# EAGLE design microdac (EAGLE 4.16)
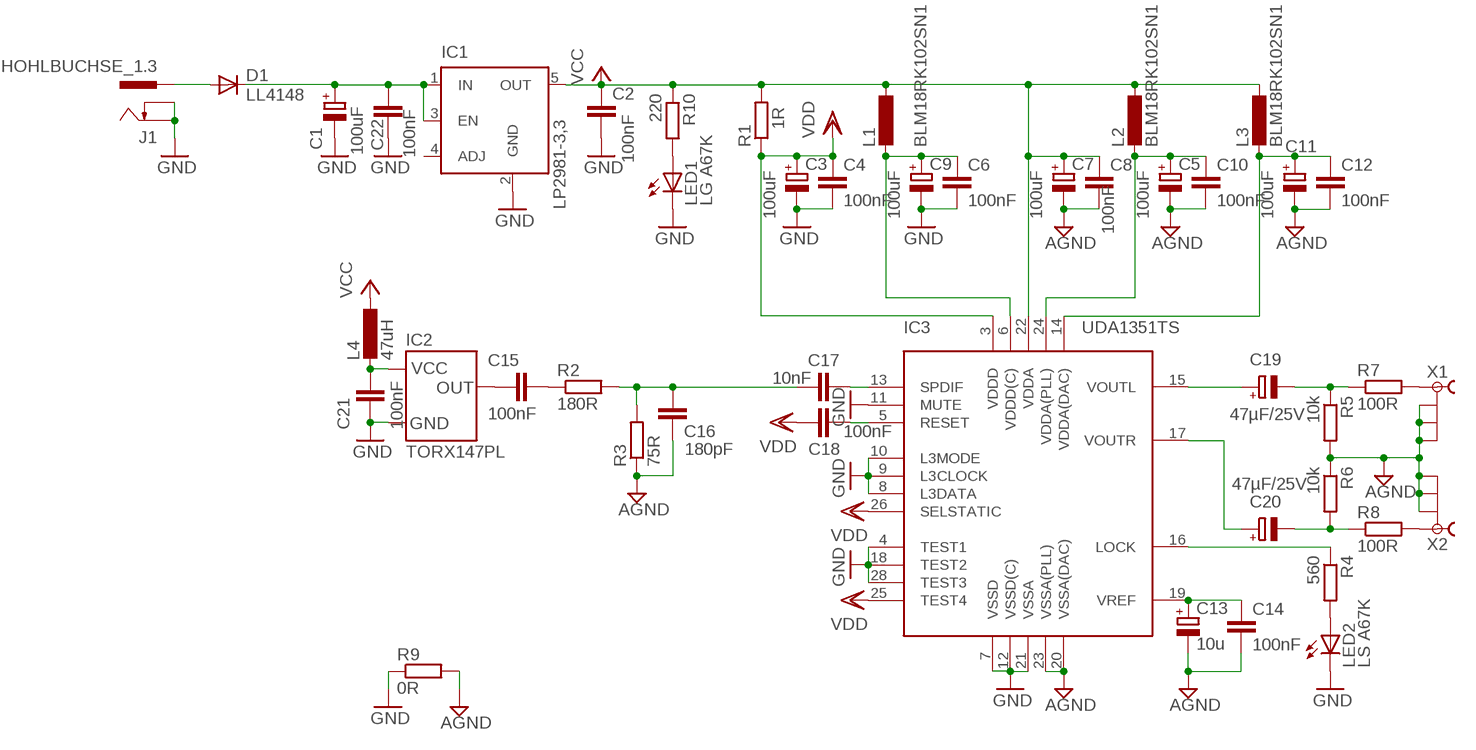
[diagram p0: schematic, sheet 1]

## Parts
C1  100uF  CPOL-EUD  [PANASONIC_D]
C2  100nF  C-EUC0603  [C0603]
C3  100uF  CPOL-EUD  [PANASONIC_D]
C4  100nF  C-EUC0603  [C0603]
C5  100uF  CPOL-EUD  [PANASONIC_D]
C6  100nF  C-EUC0603  [C0603]
C7  100uF  CPOL-EUD  [PANASONIC_D]
C8  100nF  C-EUC0603  [C0603]
C9  100uF  CPOL-EUD  [PANASONIC_D]
C10  100nF  C-EUC0603  [C0603]
C11  100uF  CPOL-EUD  [PANASONIC_D]
C12  100nF  C-EUC0603  [C0603]
C13  10u  CPOL-EUB  [PANASONIC_B]
C14  100nF  C-EUC0603  [C0603]
C15  100nF  C-EUC0603  [C0603]
C16  180pF  C-EUC0603  [C0603]
C17  10nF  C-EUC0603  [C0603]
C18  100nF  C-EUC0603  [C0603]
C19  47µF/25V  CPOL-EUD  [PANASONIC_D]
C20  47µF/25V  CPOL-EUD  [PANASONIC_D]
C21  100nF  C-EUC0603  [C0603]
C22  100nF  C-EUC0603  [C0603]
D1  LL4148  DIODE-SOD80C  [SOD80C]
IC1  LP2981-3,3  MIC5219BM5  [SOT23-5]
IC2  TORX147PL  [TOXX-PX]
IC3  UDA1351TS  [SSOP28BU]
J1  HOHLBUCHSE_1.3  [HEBO13]
L1  BLM18RK102SN1  L-EU0603  [0603]
L2  BLM18RK102SN1  L-EU0603  [0603]
L3  BLM18RK102SN1  L-EU0603  [0603]
L4  47uH  L-EU1210  [1210]
LED1  LG A67K  LEDSIDELED  [OSRAM-SIDELED]
LED2  LS A67K  LEDSIDELED  [OSRAM-SIDELED]
R1  1R  R-EU_R0603  [R0603]
R2  180R  R-EU_R0603  [R0603]
R3  75R  R-EU_R0603  [R0603]
R4  560  R-EU_R0603  [R0603]
R5  10k  R-EU_R0603  [R0603]
R6  10k  R-EU_R0603  [R0603]
R7  100R  R-EU_R0603  [R0603]
R8  100R  R-EU_R0603  [R0603]
R9  0R  R-EU_R0603  [R0603]
R10  220  R-EU_R0603  [R0603]
X1  CINCHRM5  [RM5]
X2  CINCHRM5  [RM5]

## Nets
AGND [supply]: C5.- C7.- C8.2 C10.2 C11.- C12.2 C13.- C14.2 C16.1 IC3.20(VSSA(DAC)) IC3.23(VSSA(PLL)) R3.1 R5.2 R6.1 R9.2 X1.2 X1.2@1 X1.2@2 X2.2 X2.2@1 X2.2@2
C20: C20.+ IC3.17(VOUTR)
GND: C1.- C2.2 C3.- C4.2 C6.2 C9.- C21.1 C22.2 IC1.2(GND) IC2.2(GND) IC3.4(TEST1) IC3.7(VSSD) IC3.8(L3DATA) IC3.9(L3CLOCK) IC3.10(L3MODE) IC3.11(MUTE) IC3.12(VSSD(C)) IC3.18(TEST2) IC3.21(VSSA) IC3.28(TEST3) J1.OUTER J1.SWITCH LED1.C LED2.C R9.1
N$1: LED2.A R4.2
N$2: C15.1 IC2.1(OUT)
N$3: R7.2 X1.1
N$4: R8.2 X2.1
N$5: C18.1 IC3.5(RESET)
N$6: LED1.A R10.2
N$7: D1.A J1.INNER
N$8: C19.- R5.1 R7.1
N$9: C5.+ C10.1 IC3.24(VDDA(PLL)) L2.2
N$10: C21.2 IC2.3(VCC) L4.2
N$11: C20.- R6.2 R8.1
N$13: C16.2 C17.1 R2.2 R3.2
N$16: C15.2 R2.1
N$19: IC3.16(LOCK) R4.1
N$22: C1.+ C22.1 D1.C IC1.1(IN) IC1.3(EN)
SPDIF: C17.2 IC3.13(SPDIF)
VCC: C2.1 C7.+ C8.1 IC1.5(OUT) IC3.22(VDDA) L1.1 L2.1 L3.1 L4.1 R1.2 R10.1
VDD: C3.+ C4.1 C18.2 IC3.3(VDDD) IC3.25(TEST4) IC3.26(SELSTATIC) R1.1
VDDA(DAC): C11.+ C12.1 IC3.14(VDDA(DAC)) L3.2
VDDD(C): C6.1 C9.+ IC3.6(VDDD(C)) L1.2
VOUTL: C19.+ IC3.15(VOUTL)
VREF: C13.+ C14.1 IC3.19(VREF)
Unconnected: IC1.4(ADJ)

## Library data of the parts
C1 C3 C5 C7 C9 C11 C13 C19 C20 = rcl:CPOL-EU: POLARIZED CAPACITOR, European symbol
C2 C4 C6 C8 C10 C12 C14-C18 C21 C22 = rcl:C-EU: CAPACITOR, European symbol
D1 = diode:DIODE-: DIODE
IC1 = v-reg-micrel:MIC5219BM5: VOLTAGE REGULATOR
IC2 = appsys:TORX147
IC3 = appsys:UDA1351TS
J1 = appsys:HOHLBUCHSE_1.3
L1-L4 = appsys:L-EU: INDUCTOR, European symbol
LED1 LED2 = appsys:LED: LED
R1-R10 = rcl:R-EU_: RESISTOR, European symbol
X1 X2 = appsys:CINCH: Female Cinch CONNECTOR

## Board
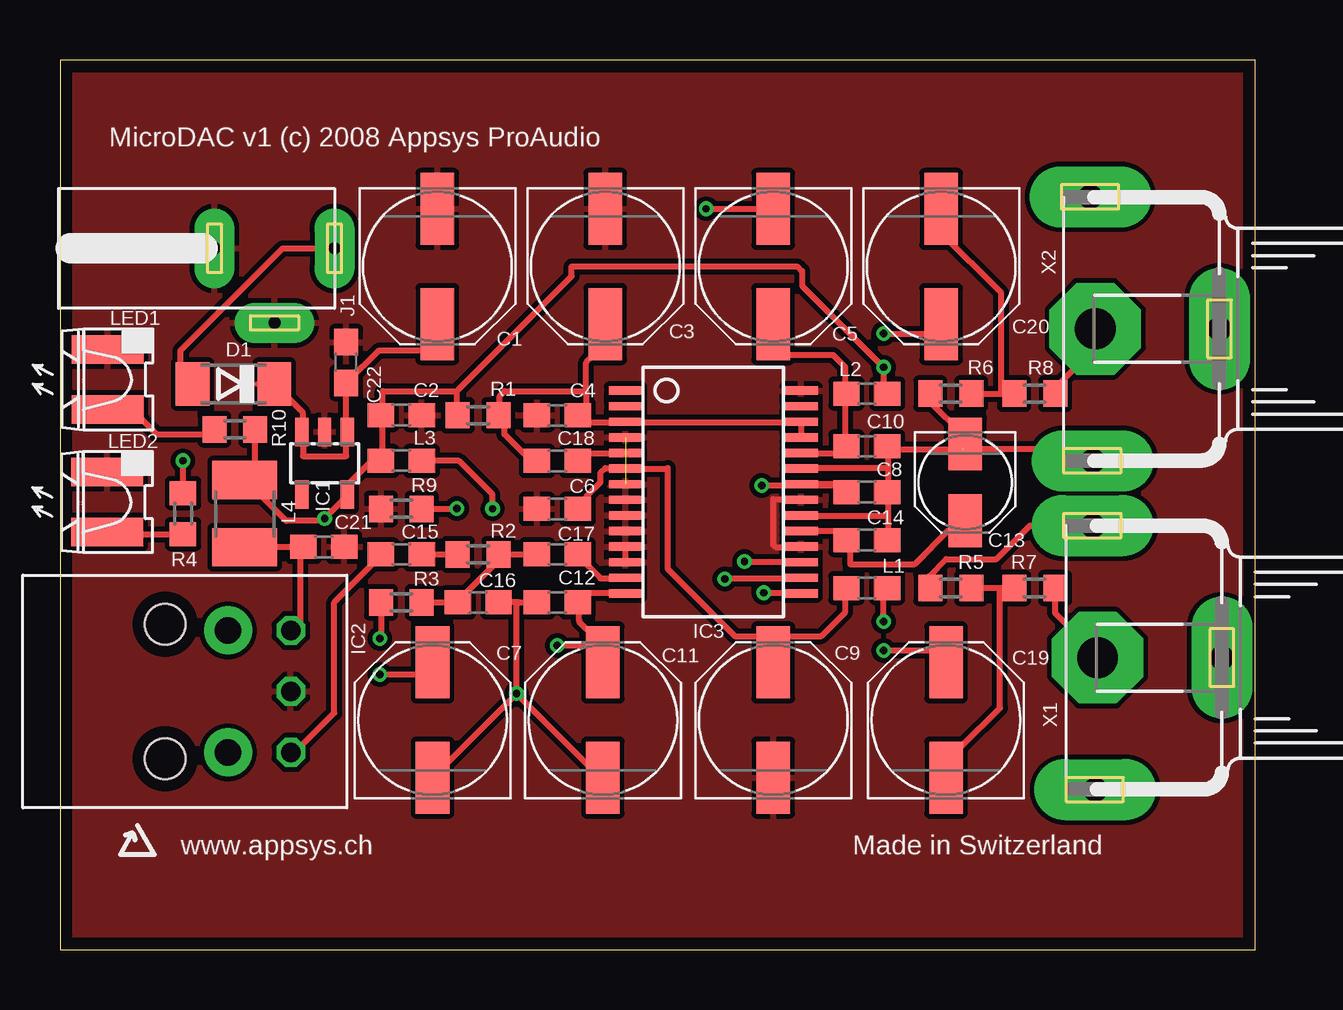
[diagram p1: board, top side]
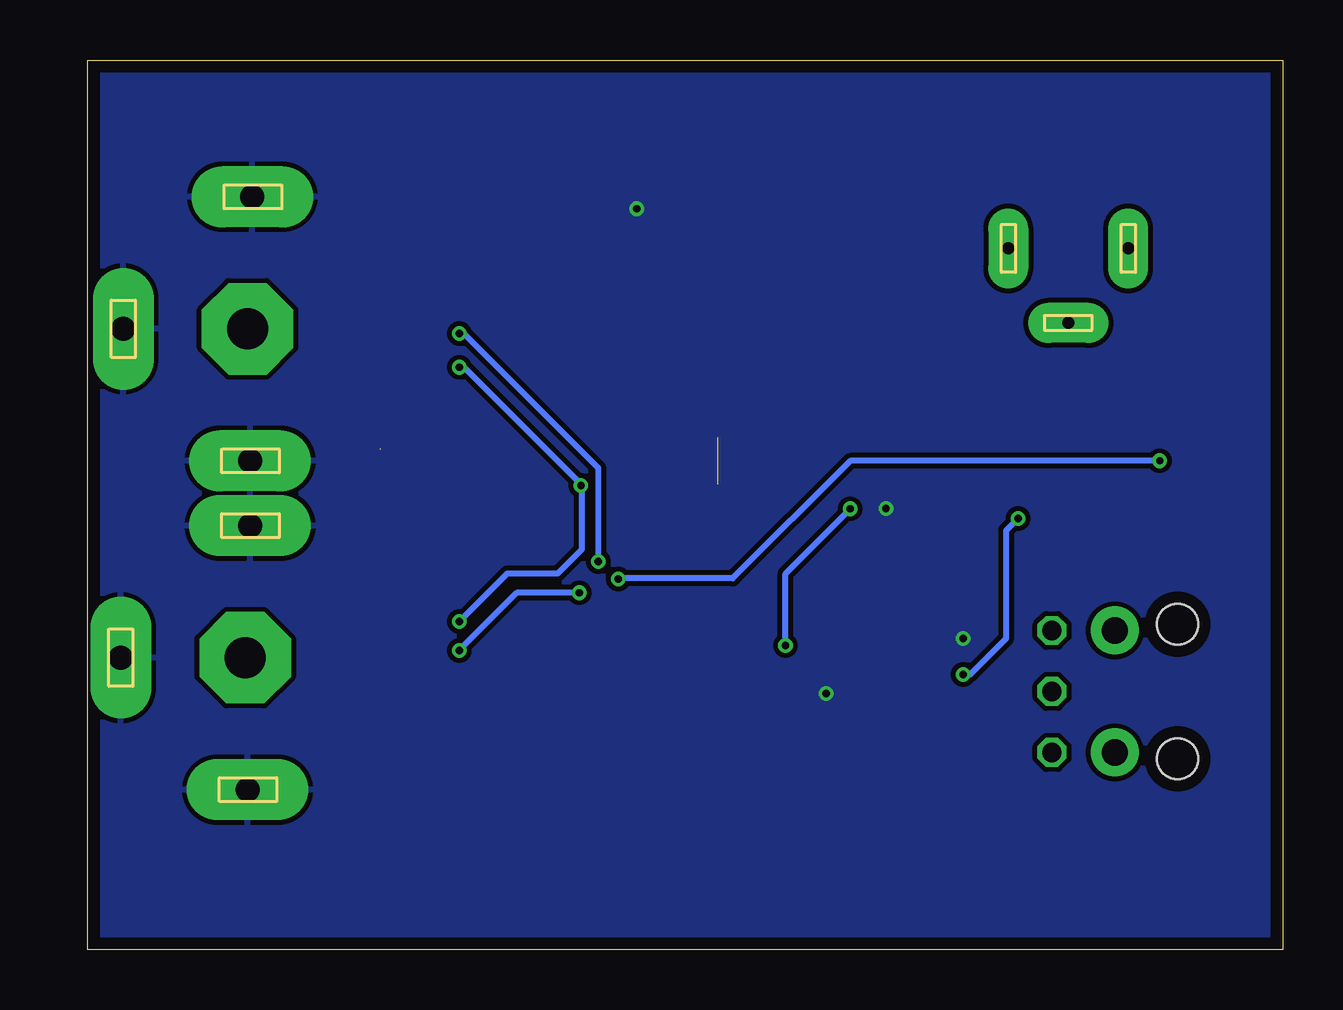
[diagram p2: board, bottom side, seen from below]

Size 49.82 x 37.07 mm. Coordinates in mm from the lower left corner, seen from the top.
Outline: 0,0 49.82,0 49.82,37.07 0,37.07 0,0
Copper layers (1*16): Top 0.035mm / dielectric 1.5mm / Bottom 0.035mm
Design rules "PCB-POOL": minimum track width 6mil, minimum drill 12mil, track to track 6mil, track to pad 6mil, pad to pad 6mil, via to via 6mil, smd to smd 6mil, copper to edge 20mil, drill to drill 8mil, minimum pad ring 8mil, minimum via ring 6mil, stop-mask expansion 3mil, vias tented up to drill 0mil, thermal gap 8mil

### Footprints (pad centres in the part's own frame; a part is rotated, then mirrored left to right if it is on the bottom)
PANASONIC_D = smd 3 x 1.4: + 2.4,0; - -2.4,0
C0603 = smd 1.1 x 1: 1 -0.85,0; 2 0.85,0
PANASONIC_B = smd 2.2 x 1.4: + 1.6,0; - -1.6,0
SOD80C = smd 1.4 x 1.8: A 1.7,0; C -1.7,0
SOT23-5 = smd 0.55 x 1.2: 1 -0.95,-1.3; 2 0,-1.3; 3 0.95,-1.3; 4 0.95,1.3; 5 -0.95,1.3
TOXX-PX = drill 0.8 octagon: 1 2.625,-2.54; 2 2.625,0; 3 2.625,2.54 | drill 1.1 pad 2 round: 4 0,2.54; 5 0,-2.54 | hole 1.7: -2.61,2.8; -2.61,-2.8
SSOP28BU = smd 0.348 x 1.397: 1 -4.225,-3.656; 2 -3.575,-3.656; 3 -2.925,-3.656; 4 -2.275,-3.656; 5 -1.625,-3.656; 6 -0.975,-3.656; 7 -0.325,-3.656; 8 0.325,-3.656; 9 0.975,-3.656; 10 1.625,-3.656; 11 2.275,-3.656; 12 2.925,-3.656; 13 3.575,-3.656; 14 4.225,-3.656; 15 4.225,3.656; 16 3.575,3.656; 17 2.925,3.656; 18 2.275,3.656; 19 1.625,3.656; 20 0.975,3.656; 21 0.325,3.656; 22 -0.325,3.656; 23 -0.975,3.656; 24 -1.625,3.656; 25 -2.275,3.656; 26 -2.925,3.656; 27 -3.575,3.656; 28 -4.225,3.656
HEBO13 = drill 0.5 pad 1.676 long: INNER 5.15,0; OUTER 0.15,0; SWITCH 2.65,-3.1
0603 = smd 1.1 x 1: 1 -0.85,0; 2 0.85,0
1210 = smd 1.6 x 2.7: 1 -1.4,0; 2 1.4,0
OSRAM-SIDELED = smd 1.2 x 3: A -1.27,0.08; C 1.23,0.08
R0603 = smd 1 x 1.1: 1 -0.85,0; 2 0.85,0
RM5 = drill 1.7 pad 3.81 octagon: 1 0,-5.18 | drill 1 pad 2.54 long: 2 5.5,-5.28; 2@1 -5.5,-5.38; 2@2 0,0

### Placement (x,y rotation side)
C1  15.73,28.47 270 top
C2  14.23,22.27 0 top
C3  22.73,28.47 270 top
C4  20.73,22.27 180 top
C5  29.73,28.47 270 top
C6  20.73,18.37 180 top
C7  15.53,9.57 90 top
C8  33.63,19.07 0 top
C9  29.73,9.57 90 top
C10  33.63,20.97 0 top
C11  22.63,9.57 90 top
C12  20.73,14.47 180 top
C13  37.73,19.47 270 top
C14  33.63,17.07 0 top
C15  14.23,16.47 0 top
C16  17.43,14.47 180 top
C17  20.73,16.47 0 top
C18  20.73,20.37 180 top
C19  36.93,9.57 90 top
C20  36.73,28.47 270 top
C21  11,16.78 180 top
C22  11.93,24.47 90 top
D1  7.23,23.57 180 top
IC1  11.03,20.27 180 top
IC2  7,10.76 0 top
IC3  27.23,19.07 270 top
J1  6.29,29.22 0 top
L1  33.63,15.07 180 top
L2  33.63,23.17 180 top
L3  14.23,20.37 0 top
L4  7.7,18.17 270 top
LED1  2.06,23.78 90 top
LED2  2.04,18.67 90 top
R1  17.43,22.27 180 top
R2  17.43,16.47 0 top
R3  14.23,14.47 0 top
R4  5.13,18.17 270 top
R5  37.13,15.07 180 top
R6  37.13,23.17 0 top
R7  40.63,15.07 0 top
R8  40.63,23.17 0 top
R9  14.23,18.37 0 top
R10  7.29,21.68 180 top
X1  48.43,12.17 270 top
X2  48.33,25.87 270 top

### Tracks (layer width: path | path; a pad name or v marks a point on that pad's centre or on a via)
AGND  (via drill 0.3)  (1 unrouted)
  Top 0.254: 34.33,17.07 C14.2 34.53,17.07 34.53,18.07 | C7.- v19.03,10.67 | 19.93,14.47 C12.2 19.13,14.47 | 19.13,14.47 C16.1 | v19.03,10.67 19.03,14.37 19.13,14.47 | 34.53,19.07 34.53,20.07 | 34.53,19.07 C8.2 | 34.53,18.07 34.53,19.07 | C10.2 34.53,20.99 | X2.2 41.53,20.37 41.03,20.87 37.63,20.87 37.63,21.47 36.28,22.82 R6.1 | 22.63,7.07 22.83,6.87 | 22.63,7.07 C11.- | v19.03,10.67 22.63,7.07 | v26.93,30.87 C5.- | R3.1 13.38,13.02 v13.33,12.97 | R5.2 36.33,15.07 36.33,15.47 36.23,15.57 36.93,16.27 39.03,16.27 40.43,17.67 X1.2@1 | v16.54,18.38 v16.53,18.38 v16.53,18.37 R9.2 | 34.53,20.97 C10.2 | 34.53,20.07 34.53,20.97 | 37.53,20.84 37.63,20.84 | 37.63,20.84 37.66,20.84 | 37.53,20.84 37.53,21.27 | 34.53,20.84 34.53,20.47 | 34.53,20.84 37.53,20.84 | C10.2 34.53,20.97 | 34.53,20.97 34.53,20.84 | IC3.23 30.83,20.04 30.83,20.07 34.53,20.07 | 34.53,18.07 30.93,18.07 30.93,18.09 IC3.20 | 37.63,20.84 37.63,20.77 37.73,20.77 C13.-
  pour Bottom (isolate 0.203): 0.08,37.02 -0.02,-0.03 49.43,-0.03 49.43,37.02
C20  (via drill 0.3)
  Top 0.254: IC3.17 30.83,16.14 30.83,16.17 v28.53,16.17 | v34.33,25.67 36.73,25.67 C20.+
  Bottom 0.254: v28.53,16.17 28.53,20.07 34.13,25.67 v34.33,25.67
GND  (1 unrouted)
  Top 0.254: IC3.12 23.55,16.14 23.53,16.17 23.57,16.21 IC3.11 | IC3.18 30.83,16.79 30.83,16.77 29.83,16.77 29.73,16.87 29.73,18.77 30.83,18.77 30.83,18.74 IC3.21
  pour Top (isolate 0.203): 0.08,37.07 49.38,37.07 49.38,-0.08 -0.02,0.02
N$1
  Top 0.254: LED2.A 2.03,17.47 2.18,17.32 R4.2
N$2
  Top 0.254: IC2.1 9.78,8.22 11.43,9.87 11.43,14.47 13.43,16.47 C15.1
N$3
  Top 0.254: 43.33,12.17 43.53,11.97 | X1.1 43.33,12.17 | R7.2 41.48,14.02 43.33,12.17
N$4
  Top 0.254: R8.2 41.48,23.42 43.13,25.07 43.13,25.87 X2.1
N$5
  Top 0.254: 21.68,20.47 21.68,20.32 | 21.68,20.47 21.68,20.64 | 21.53,20.47 21.68,20.47 | 21.53,20.47 21.53,20.37 C18.1 | IC3.5 21.53,20.7 21.53,20.47
N$6
  Top 0.254: LED1.A 2.03,22.47 3.03,22.47 4.03,21.47 6.53,21.47 | 6.53,21.47 6.52,21.48 | R10.2 6.53,21.68 6.53,21.47
N$7
  Top 0.254: J1.INNER 9.28,29.22 5.03,24.97 5.03,23.57 | 5.03,23.57 D1.A | 5.03,23.47 5.03,23.57
N$8
  Top 0.254: R7.1 39.53,15.07 | R7.1 39.83,15.07 | 39.23,15.07 R5.1 | 39.23,15.07 R7.1 | 39.23,15.07 39.18,15.02 39.18,10.07 37.58,8.47 36.93,8.47 C19.-
N$9
  Top 0.254: 32.73,23.22 32.73,24.27 32.23,24.77 29.73,24.77 C5.+ | 32.73,20.87 32.73,20.97 C10.1 | 32.73,23.22 L2.2 | 32.73,20.87 32.76,20.89 C10.1 | 32.73,20.87 32.73,23.22 | C10.1 32.76,20.7 32.73,20.67 32.7,20.7 IC3.24
N$10
  Top 0.254: IC2.3 9.62,13.28 9.63,13.27 10.03,13.67 10.03,16.77 | 10.03,16.77 10.03,16.78 | 10.03,16.77 10.04,16.78 C21.2 | 10.03,16.77 L4.2
N$11
  Top 0.254: 36.68,29.92 39.23,27.37 39.23,23.17 | 36.68,29.92 36.33,30.27 | 39.23,23.17 R8.1 | R6.2 39.23,23.17 | 36.68,29.92 36.73,29.92 C20.-
N$13
  Top 0.254: R3.2 16.53,14.47 | R2.2 18.13,16.47 | 19.93,16.47 C17.1 R2.2 | 18.33,16.37 18.38,16.42 | R2.2 18.28,16.37 18.33,16.37 | 16.53,14.47 16.53,14.57 | 16.53,14.47 C16.2 | 18.33,16.37 18.33,16.27 16.53,14.47
N$16
  Top 0.254: 16.73,16.47 R2.1 C15.2
N$19  (via drill 0.3)
  Top 0.254: R4.1 v5.13,20.37 | v27.71,15.45 27.71,15.47 30.89,15.47 IC3.16
  Bottom 0.254: v5.13,20.37 18.03,20.37 22.93,15.47 27.73,15.47 v27.71,15.45 27.68,15.47
N$22
  Top 0.254: C1.+ 15.63,26.17 15.63,25.07 15.53,24.97 13.3,24.97 C22.1 | C22.1 11.93,23.84 | 11.93,21.97 C22.1 | D1.C 8.23,23.57 | D1.C 8.48,23.57 | 10.13,21.57 10.13,20.57 11.93,20.57 11.93,21.97 | 11.93,21.97 | IC1.3 10.13,21.57 | IC1.3 | D1.C 10.13,22.37 10.13,21.92 | 10.13,21.57 10.13,21.92 | 11.93,21.97 12.03,21.97 12.03,21.57 | 12.03,21.57 IC1.1 | 10.13,21.92 10.08,21.97 10.03,21.97 10.03,21.62 IC1.3 | IC1.1 12.03,21.57 | IC1.1 | 11.93,21.97 11.93,21.57 IC1.1
SPDIF
  Top 0.254: C17.2 21.58,16.42 22.53,15.47 23.53,15.47 23.55,15.5 IC3.13
VCC  (via drill 0.3)
  Top 0.254: 16.53,23.27 13.45,23.27 13.45,22.27 C2.1 13.33,22.27 13.45,22.15 13.45,20.37 13.43,20.37 | R1.2 16.53,22.27 16.53,23.27 | v13.33,11.47 15.53,11.47 C7.+ 15.53,12.07 | 16.53,23.27 21.33,28.07 21.33,28.47 30.73,28.47 30.93,28.27 30.93,27.67 v34.33,24.27 34.33,23.22 | v29.26,19.34 33.03,19.34 | 34.33,23.22 34.33,23.12 | L1.1 34.33,15.07 v34.33,13.67 | 13.43,20.37 13.53,20.37 | R10.1 8.14,19.98 7.73,19.57 | 7.73,19.57 L4.1 | 7.73,19.57 9.43,17.87 10.93,17.87 v11.03,17.97 11.93,18.87 | 11.98,19.37 12.03,19.37 12.03,19.07 | L3.1 12.98,20.37 11.98,19.37 | L3.1 13.43,20.37 | L2.1 34.43,23.17 34.43,23.22 34.33,23.22 | 32.83,19.39 IC3.22 | C8.1 32.83,19.07 32.83,19.39 | 33.03,19.34 33.03,18.97 | 33.03,19.34 | 32.83,19.39 33.03,19.39 33.03,19.34 | 11.93,18.87 11.93,18.92 | 11.93,18.92 IC1.5 | 11.98,19.37 11.93,19.32 11.93,18.97 | 11.93,18.92 11.93,18.97 | 11.93,18.97 IC1.5 | IC1.5 | 11.93,18.87 11.93,18.97 | L3.1 13.53,20.37 | 13.53,20.37 13.53,20.47 | 11.93,18.97 IC1.5 | IC1.5 | IC1.5 11.98,19.37 | 11.93,18.97 IC1.5 | 13.4,20.34 13.4,20.27 13.53,20.27 13.53,20.37
  Bottom 0.254: v34.33,13.67 32.33,15.67 30.23,15.67 29.23,16.67 29.23,19.32 v29.26,19.34 29.23,19.37 34.13,24.27 v34.33,24.27 | v11.03,17.97 11.53,17.47 11.53,12.97 13.03,11.47 v13.33,11.47
VDD
  Top 0.254: 21.93,23.27 21.93,24.47 22.73,25.27 C3.+ | 21.93,23.27 18.53,23.27 18.33,23.07 18.33,22.27 | 23.57,21.97 23.63,21.97 | 21.93,23.27 21.93,21.97 | 21.93,21.97 23.53,21.97 | 23.53,21.97 23.57,21.97 | 30.89,21.97 30.93,21.97 | 30.89,21.97 IC3.26 30.89,21.37 | 23.57,21.97 30.89,21.97 | 30.89,21.37 IC3.25 | 30.89,21.37 30.93,21.37 | C4.1 21.76,22.27 | 18.33,22.27 R1.1 | 18.33,22.27 18.53,22.07 18.53,21.47 19.51,20.49 19.8,20.49 19.8,20.34 19.83,20.34 | IC3.3 23.55,21.99 23.53,21.97 | C4.1 21.93,22.27 21.93,21.97 | 19.83,20.34 19.83,20.37 C18.2 | 19.83,20.27 19.83,20.34 | C4.1 21.53,22.27 | 21.64,22.36 21.64,22.27 21.53,22.27 | 21.53,22.27 21.53,22.36
VDDA(DAC)  (via drill 0.3)
  Top 0.254: C12.1 21.53,14.47 | 22.63,12.67 v20.73,12.67 | 22.63,12.67 22.73,12.67 | v18.03,18.37 18.03,18.97 16.63,20.37 L3.2 | C12.1 21.61,14.87 23.57,14.87 IC3.14 | C12.1 21.63,14.47 21.63,13.75 21.66,13.75 21.66,13.65 22.58,12.72 | 22.58,12.72 22.63,12.67 | 22.63,12.72 22.63,12.77 | 22.63,12.72 22.58,12.72 | C11.+ 22.63,12.72
  Bottom 0.254: v18.03,18.37 20.73,15.67 v20.73,12.67
VDDD(C)
  Top 0.254: 25.33,19.97 25.33,15.87 28.13,13.07 29.53,13.07 | 25.33,19.97 25.33,20.07 | C9.+ 29.73,12.07 29.53,12.27 29.53,13.07 | 29.53,13.07 31.73,13.07 32.73,14.07 32.73,15.07 L1.2 | C6.1 21.83,18.37 21.83,18.47 21.93,18.47 21.93,18.87 22.53,19.47 22.53,19.87 22.73,20.07 23.63,20.07 23.63,20.04 IC3.6 | IC3.6 23.57,20.01 | IC3.6 25.33,20.04 25.33,19.97
VOUTL  (via drill 0.3)
  Top 0.254: v34.33,12.47 36.93,12.47 C19.+ | IC3.15 30.83,14.85 30.83,14.87 v29.33,14.87
  Bottom 0.254: v29.33,14.87 31.93,14.87 v34.33,12.47
VREF
  Top 0.254: IC3.19 32.73,17.45 32.73,17.07 C14.1 33.03,17.07 32.93,16.97 32.93,16.07 35.63,16.07 37.03,17.47 37.33,17.47 C13.+

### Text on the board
tNames: MicroDAC v1 (c) 2008 Appsys ProAudio | www.appsys.ch | Made in Switzerland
